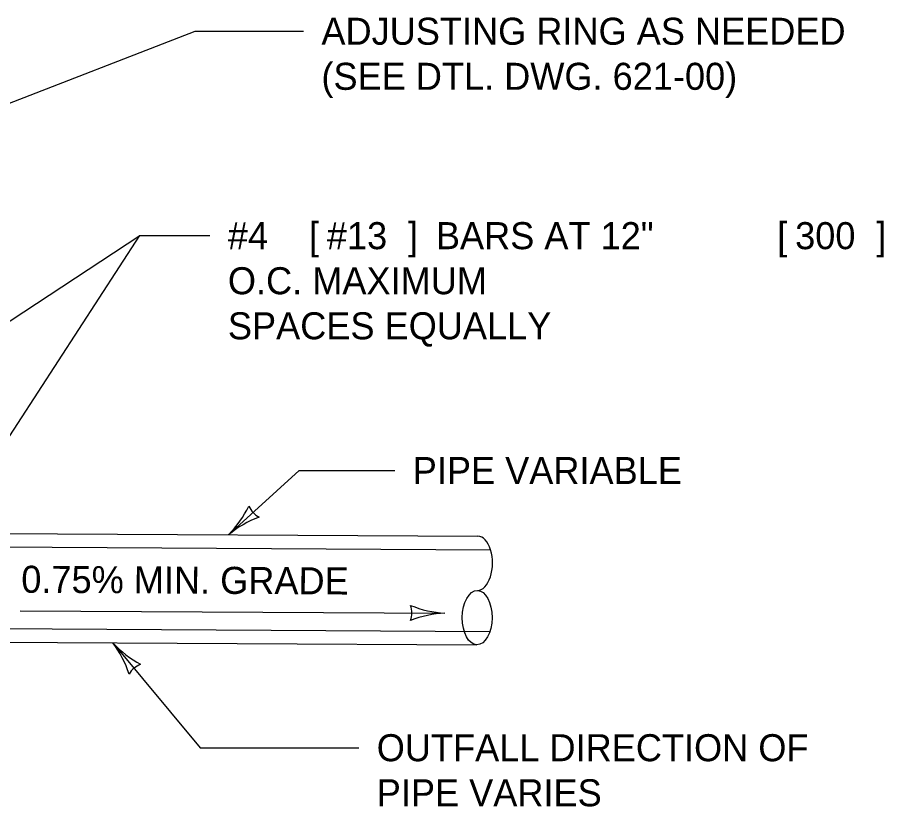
# Model space of a CAD drawing. Extents: x 49991.4 to 50041.6, y 49987.6 to 50011.4.
# Drawn here: x 50039.67 to 50041.593, y 49991.991 to 49993.742 of the extents above; entities that cross this region are included whole.
import ezdxf

# ---------------------------------------------------------------- set-up
doc = ezdxf.new("R2010")
doc.units = 0
for name, color, linetype in [('Level 1', 7, 'Continuous'), ('Level 2', 7, 'Continuous'), ('Level 3', 7, 'Continuous')]:
    doc.layers.add(name, color=color, linetype=linetype)

msp = doc.modelspace()

# ---------------------------------------------------------------- linework, layer by layer
at = {"layer": 'Level 1'}
for p, q in [((50039.4779, 49992.598), (50040.6924, 49992.5913)), ((50039.4779, 49992.568), (50040.7207, 49992.5611)), ((50039.4779, 49992.3868), (50040.7191, 49992.3799)), ((50039.4779, 49992.3568), (50040.6903, 49992.3501))]:
    msp.add_line(p, q, dxfattribs=at)
msp.add_ellipse((50040.6919, 49992.531), major_axis=(-0.0005, -0.0603), ratio=0.547626, start_param=6.283163, end_param=9.424778, dxfattribs=at)
msp.add_ellipse((50040.6908, 49992.4104), major_axis=(0.0005, 0.0603), ratio=0.547626, dxfattribs=at)
at = {"layer": 'Level 3'}
for p, q in [((50039.5866, 49993.5268), (50040.0652, 49993.7116)), ((50040.0652, 49993.7116), (50040.3051, 49993.7116)), ((50039.5679, 49993.0128), (50039.9422, 49993.258)), ((50039.5679, 49992.6828), (50039.9422, 49993.258)), ((50039.9422, 49993.258), (50040.0975, 49993.258)), ((50040.1389, 49992.5944), (50040.2958, 49992.7368)), ((50040.2958, 49992.7368), (50040.5078, 49992.7368)), ((50039.6766, 49992.4257), (50040.6191, 49992.4204)), ((50039.8823, 49992.3546), (50040.076, 49992.1218)), ((50040.076, 49992.1218), (50040.4279, 49992.1218))]:
    msp.add_line(p, q, dxfattribs=at)
for centre, radius, start, end in [((50039.974, 49992.7589), 0.233, 315.0626, 334.3125), ((50039.974, 49992.7589), 0.233, 315.0626, 334.3125), ((50040.2339, 49992.6805), 0.0548, 204.3742, 240.0965), ((50040.2339, 49992.6805), 0.0548, 204.3742, 240.0965), ((50040.2815, 49992.4237), 0.2223, 109.6913, 129.8749), ((50040.2815, 49992.4237), 0.2223, 109.6913, 129.8749), ((50040.4909, 49992.4212), 0.0548, 341.8218, 17.5442), ((50040.6295, 49992.6425), 0.2223, 247.139, 267.3225), ((50040.6293, 49992.1877), 0.233, 92.5103, 111.7602), ((50039.7057, 49992.2195), 0.2223, 17.2282, 37.4117), ((50040.0538, 49992.5123), 0.233, 222.5995, 241.8494), ((50039.7057, 49992.2195), 0.2223, 17.2282, 37.4117), ((50040.0538, 49992.5123), 0.233, 222.5995, 241.8494), ((50039.9643, 49992.256), 0.0548, 111.911, 147.6334), ((50039.9643, 49992.256), 0.0548, 111.911, 147.6334)]:
    msp.add_arc(centre, radius, start, end, dxfattribs=at)

# ---------------------------------------------------------------- texts
at = {"layer": 'Level 2'}
for s, rotation, p in [('ADJUSTING RING AS NEEDED', 360, (50040.3451, 49993.6816)), ('(SEE DTL. DWG. 621-00)', 360, (50040.3451, 49993.5816)), ('#4 ', 360, (50040.1375, 49993.228)), ('[', 360, (50040.3175, 49993.228)), ('#13', 360, (50040.3572, 49993.228)), (']', 360, (50040.5372, 49993.228)), (' BARS AT 12" ', 360, (50040.5769, 49993.228)), ('[', 360, (50041.3569, 49993.228)), ('300', 360, (50041.3966, 49993.228)), (']', 360, (50041.5766, 49993.228)), ('O.C. MAXIMUM', 360, (50040.1375, 49993.128)), ('SPACES EQUALLY', 360, (50040.1375, 49993.028)), ('PIPE VARIABLE', 360, (50040.5478, 49992.7068)), ('0.75% MIN. GRADE', 359.683, (50039.6788, 49992.4657)), ('OUTFALL DIRECTION OF', 360, (50040.4679, 49992.0918)), ('PIPE VARIES', 360, (50040.4679, 49991.9918))]:
    msp.add_text(s, height=0.06, rotation=rotation, dxfattribs=at).set_placement(p)

doc.saveas('drawing.dxf')
